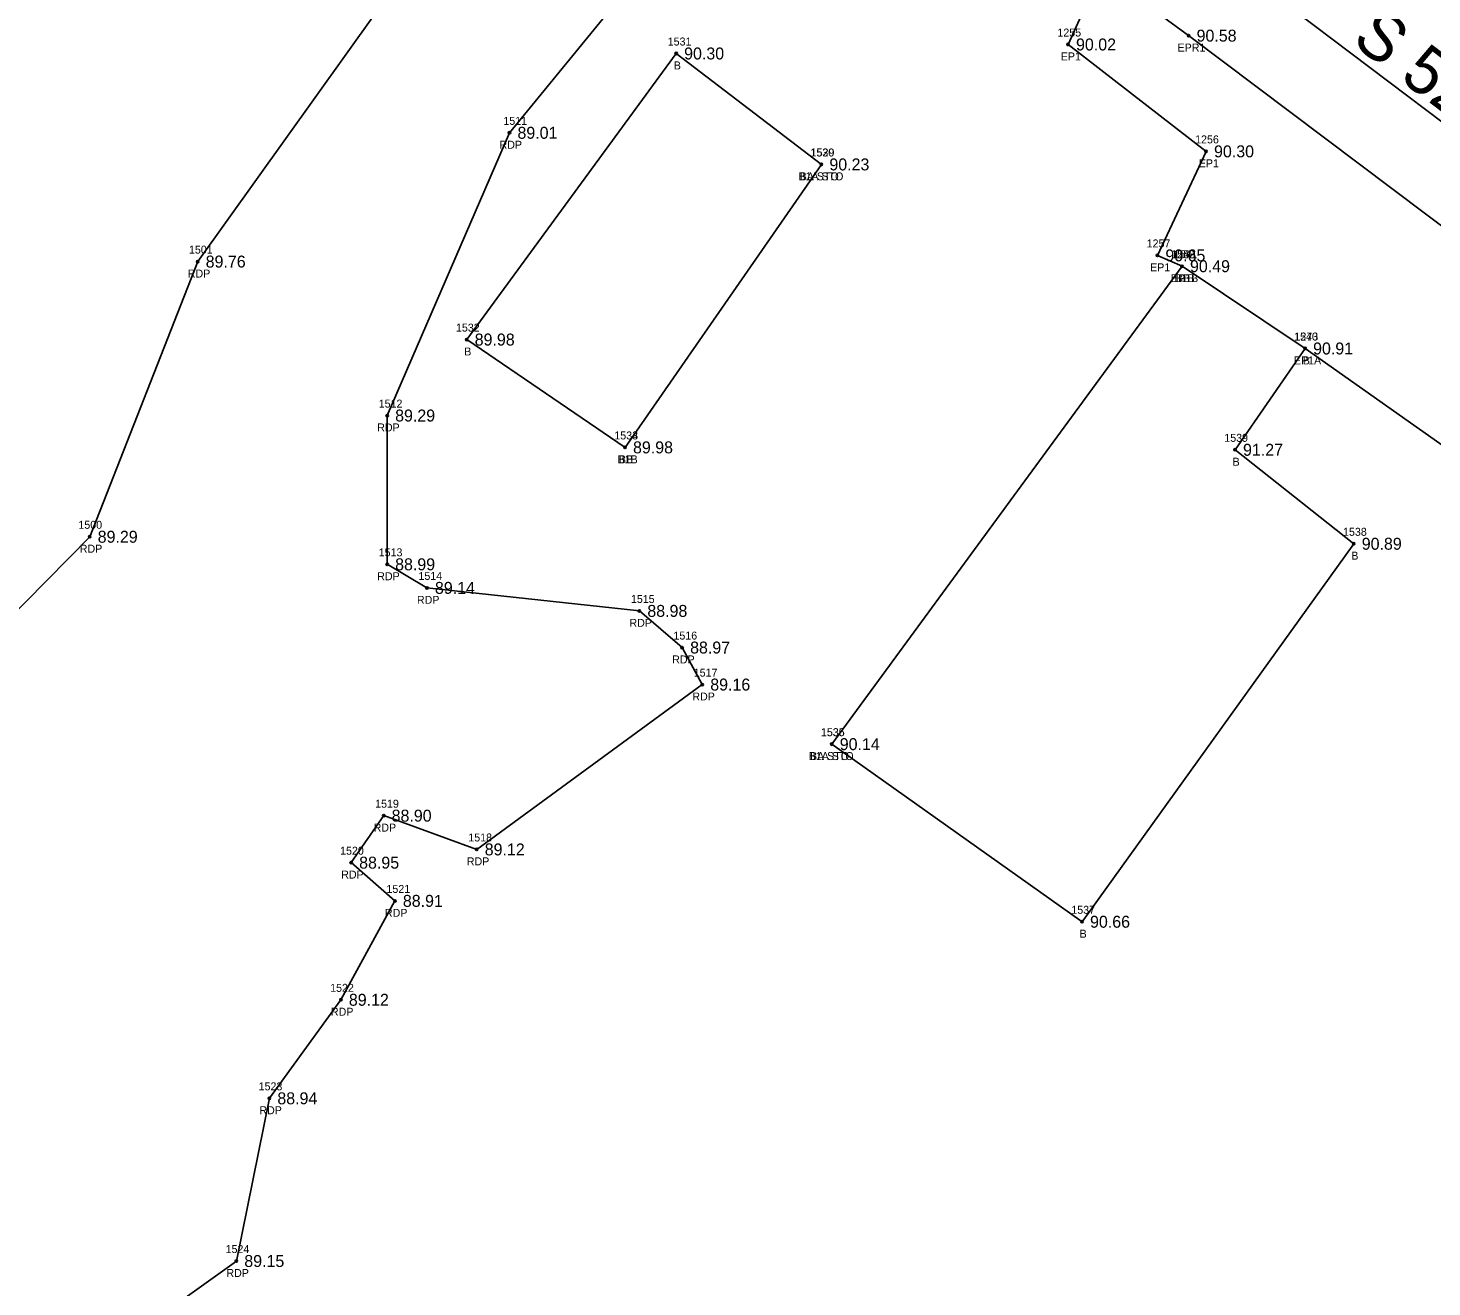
# Model space of a CAD drawing. Extents: x 2529517 to 2532038, y 935000 to 936944.
# Drawn here: x 2531691.2 to 2531867.5, y 936109.2 to 936267.3 of the extents above; entities that cross this region are included whole.
import ezdxf

# ---------------------------------------------------------------- set-up
doc = ezdxf.new("R2010")
doc.units = 0
for name, color, linetype in [('Default', 7, 'Continuous'), ('RD_EX_Bldg', 7, 'Continuous'), ('RD_EX_Bldg_txCode', 7, 'Continuous'), ('RD_EX_DR_ErosCtrl', 7, 'Continuous'), ('RD_EX_DR_ErosCtrl_txCode', 7, 'Continuous'), ('RD_EX_Road', 7, 'Continuous'), ('RD_EX_Road_txCode', 7, 'Continuous'), ('RD_EX_TX_Bldg_ELEV', 7, 'Continuous'), ('RD_EX_TX_DR_ErosCtrl_ELEV', 7, 'Continuous'), ('RD_EX_TX_Road_ELEV', 7, 'Continuous'), ('RD_HC_Cl', 7, 'Continuous'), ('RD_HC_Data', 7, 'Continuous'), ('RD_SMD_Locator', 7, 'Continuous')]:
    doc.layers.add(name, color=color, linetype=linetype)

msp = doc.modelspace()

# ---------------------------------------------------------------- linework, layer by layer
at = {"layer": 'Default'}
msp.add_line((2531759.99, 936337.77), (2531999.23, 936156.76), dxfattribs=at)
at = {"layer": 'RD_EX_Bldg'}
for p, q in [((2531790.82, 936250.17), (2531766.16, 936214.64)), ((2531792.12, 936177.38), (2531836.1, 936237.39))]:
    msp.add_line(p, q, dxfattribs=at)
for points in [[(2531790.82, 936250.17), (2531772.58, 936264.1), (2531746.28, 936228.18), (2531766.16, 936214.64)], [(2531792.12, 936177.38), (2531823.55, 936155.08), (2531857.67, 936202.54), (2531842.76, 936214.34), (2531851.56, 936227.06), (2531836.1, 936237.39)]]:
    msp.add_lwpolyline(points, dxfattribs=at)
at = {"layer": 'RD_EX_DR_ErosCtrl'}
for points in [[(2531680.04, 936184.26), (2531698.94, 936203.42), (2531712.5, 936237.97), (2531745.88, 936284.65)], [(2531765.86, 936271.49), (2531751.65, 936254.14), (2531736.29, 936218.64), (2531736.29, 936199.96), (2531741.29, 936197), (2531767.96, 936194.11), (2531773.33, 936189.51), (2531775.86, 936184.86), (2531747.54, 936164.16), (2531735.85, 936168.4), (2531731.77, 936162.5), (2531737.26, 936157.7), (2531730.48, 936145.28), (2531721.5, 936132.91), (2531717.35, 936112.48), (2531678.42, 936084.68)]]:
    msp.add_lwpolyline(points, dxfattribs=at)
at = {"layer": 'RD_EX_Road'}
for points in [[(2531730.37, 936304.55), (2531747.09, 936311.1), (2531758.83, 936311.42), (2531770.03, 936309.95), (2531779.92, 936307.38), (2531789.77, 936300.82), (2531836.93, 936266.34), (2531918.06, 936205.29), (2531926.11, 936199.32), (2531961.6, 936172.59), (2531979.77, 936158.9), (2531999.31, 936144.02)], [(2531789.77, 936300.82), (2531790.01, 936296.25), (2531786.83, 936289.89), (2531786.44, 936288.37), (2531799.22, 936278.89), (2531801.03, 936276.89), (2531802.47, 936278.74), (2531808.91, 936274.72), (2531810.53, 936277.69), (2531813.62, 936279.43), (2531824.83, 936271.92), (2531821.79, 936265.23), (2531839.12, 936251.81), (2531833.01, 936238.75), (2531836.1, 936237.39)], [(2531851.56, 936227.06), (2531887.12, 936201.98), (2531888.05, 936195.78), (2531900.78, 936186.47), (2531908.4, 936194.18), (2531912.55, 936196.67), (2531920.21, 936199.08), (2531926.11, 936199.32)]]:
    msp.add_lwpolyline(points, dxfattribs=at)
at = {"layer": 'RD_HC_Cl'}
msp.add_line((2531759.99, 936337.77), (2531999.23, 936156.76), dxfattribs=at)
at = {"layer": 'RD_SMD_Locator'}
for centre in [(2531836.93, 936266.34), (2531772.58, 936264.1), (2531821.79, 936265.23), (2531751.65, 936254.14), (2531839.12, 936251.81), (2531790.82, 936250.17), (2531790.82, 936250.17), (2531712.5, 936237.97), (2531833.01, 936238.75), (2531836.1, 936237.39), (2531836.1, 936237.39), (2531836.1, 936237.39), (2531746.28, 936228.18), (2531851.56, 936227.06), (2531851.56, 936227.06), (2531736.29, 936218.64), (2531766.16, 936214.64), (2531766.16, 936214.64), (2531842.76, 936214.34), (2531698.94, 936203.42), (2531857.67, 936202.54), (2531736.29, 936199.96), (2531741.29, 936197), (2531767.96, 936194.11), (2531773.33, 936189.51), (2531775.86, 936184.86), (2531792.12, 936177.38), (2531792.12, 936177.38), (2531735.85, 936168.4), (2531747.54, 936164.16), (2531731.77, 936162.5), (2531737.26, 936157.7), (2531823.55, 936155.08), (2531730.48, 936145.28), (2531721.5, 936132.91), (2531717.35, 936112.48)]:
    msp.add_circle(centre, 0.15, dxfattribs=at)

# ---------------------------------------------------------------- texts
at = {"layer": 'RD_EX_Bldg_txCode'}
for s, p in [('1531', (2531771.52, 936265.1)), ('B', (2531772.28, 936262.1)), ('1530', (2531789.44, 936251.17)), ('1529', (2531789.48, 936251.17)), ('B1A STO', (2531787.93, 936248.17)), ('BA STO', (2531788.09, 936248.17)), ('1542', (2531834.76, 936238.39)), ('1541', (2531835.04, 936238.39)), ('B1B', (2531835.16, 936235.39)), ('BB', (2531835.32, 936235.39)), ('1532', (2531744.93, 936229.18)), ('1540', (2531850.18, 936228.06)), ('B', (2531745.97, 936226.18)), ('B', (2531851.26, 936225.06)), ('1533', (2531764.82, 936215.64)), ('1534', (2531764.82, 936215.64)), ('1539', (2531841.41, 936215.34)), ('B1B', (2531765.22, 936212.64)), ('BB', (2531765.38, 936212.64)), ('B', (2531842.45, 936212.34)), ('1538', (2531856.32, 936203.54)), ('B', (2531857.36, 936200.54)), ('1536', (2531790.75, 936178.38)), ('1535', (2531790.77, 936178.38)), ('B1A STO', (2531789.22, 936175.38)), ('BA STO', (2531789.38, 936175.38)), ('1537', (2531822.2, 936156.08)), ('B', (2531823.24, 936153.08))]:
    msp.add_text(s, height=1, dxfattribs=at).set_placement(p)
at = {"layer": 'RD_EX_DR_ErosCtrl_txCode'}
for s, p in [('1511', (2531750.88, 936255.14)), ('RDP', (2531750.4, 936252.14)), ('1501', (2531711.4, 936238.97)), ('RDP', (2531711.25, 936235.97)), ('1512', (2531735.23, 936219.64)), ('RDP', (2531735.04, 936216.64)), ('1500', (2531697.52, 936204.42)), ('RDP', (2531697.69, 936201.42)), ('1513', (2531735.23, 936200.96)), ('RDP', (2531735.04, 936197.96)), ('1514', (2531740.22, 936198)), ('RDP', (2531740.03, 936195)), ('1515', (2531766.9, 936195.11)), ('RDP', (2531766.71, 936192.11)), ('1516', (2531772.24, 936190.51)), ('RDP', (2531772.08, 936187.51)), ('1517', (2531774.79, 936185.86)), ('RDP', (2531774.61, 936182.86)), ('1519', (2531734.78, 936169.4)), ('RDP', (2531734.59, 936166.4)), ('1518', (2531746.48, 936165.16)), ('1520', (2531730.38, 936163.5)), ('RDP', (2531746.29, 936162.16)), ('RDP', (2531730.52, 936160.5)), ('1521', (2531736.2, 936158.7)), ('RDP', (2531736.01, 936155.7)), ('1522', (2531729.13, 936146.28)), ('RDP', (2531729.23, 936143.28)), ('1523', (2531720.15, 936133.91)), ('RDP', (2531720.24, 936130.91)), ('1524', (2531716, 936113.48)), ('RDP', (2531716.1, 936110.48))]:
    msp.add_text(s, height=1, dxfattribs=at).set_placement(p)
at = {"layer": 'RD_EX_Road_txCode'}
for s, p in [('1255', (2531820.45, 936266.23)), ('EP1', (2531820.87, 936263.23)), ('EPR1', (2531835.54, 936264.34)), ('1256', (2531837.75, 936252.81)), ('EP1', (2531838.2, 936249.81)), ('1257', (2531831.66, 936239.75)), ('EP1', (2531832.09, 936236.75)), ('1258', (2531834.76, 936238.39)), ('EP1B', (2531834.71, 936235.39)), ('1273', (2531850.22, 936228.06)), ('EP1A', (2531850.15, 936225.06))]:
    msp.add_text(s, height=1, dxfattribs=at).set_placement(p)
at = {"layer": 'RD_EX_TX_Bldg_ELEV'}
for s, p in [('90.30', (2531773.58, 936263.35)), ('90.23', (2531791.82, 936249.42)), ('90.23', (2531791.82, 936249.42)), ('90.49', (2531837.1, 936236.64)), ('90.49', (2531837.1, 936236.64)), ('89.98', (2531747.28, 936227.43)), ('90.91', (2531852.56, 936226.31)), ('89.98', (2531767.16, 936213.89)), ('89.98', (2531767.16, 936213.89)), ('91.27', (2531843.76, 936213.59)), ('90.89', (2531858.67, 936201.79)), ('90.14', (2531793.12, 936176.63)), ('90.14', (2531793.12, 936176.63)), ('90.66', (2531824.55, 936154.33))]:
    msp.add_text(s, height=1.5, dxfattribs=at).set_placement(p)
at = {"layer": 'RD_EX_TX_DR_ErosCtrl_ELEV'}
for s, p in [('89.01', (2531752.65, 936253.39)), ('89.76', (2531713.5, 936237.22)), ('89.29', (2531737.29, 936217.89)), ('89.29', (2531699.94, 936202.67)), ('88.99', (2531737.29, 936199.21)), ('89.14', (2531742.29, 936196.25)), ('88.98', (2531768.96, 936193.36)), ('88.97', (2531774.33, 936188.76)), ('89.16', (2531776.86, 936184.11)), ('88.90', (2531736.85, 936167.65)), ('89.12', (2531748.54, 936163.41)), ('88.95', (2531732.77, 936161.75)), ('88.91', (2531738.26, 936156.95)), ('89.12', (2531731.48, 936144.53)), ('88.94', (2531722.5, 936132.16)), ('89.15', (2531718.35, 936111.73))]:
    msp.add_text(s, height=1.5, dxfattribs=at).set_placement(p)
at = {"layer": 'RD_EX_TX_Road_ELEV'}
for s, p in [('90.02', (2531822.79, 936264.48)), ('90.58', (2531837.93, 936265.59)), ('90.30', (2531840.12, 936251.06)), ('90.65', (2531834.01, 936238)), ('90.49', (2531837.1, 936236.64)), ('90.91', (2531852.56, 936226.31))]:
    msp.add_text(s, height=1.5, dxfattribs=at).set_placement(p)
at = {"layer": 'RD_HC_Data'}
msp.add_text('S 52%%d 53\' 18" E', height=6, rotation=322.8882, dxfattribs=at).set_placement((2531857.25, 936265.44))

doc.saveas('drawing.dxf')
